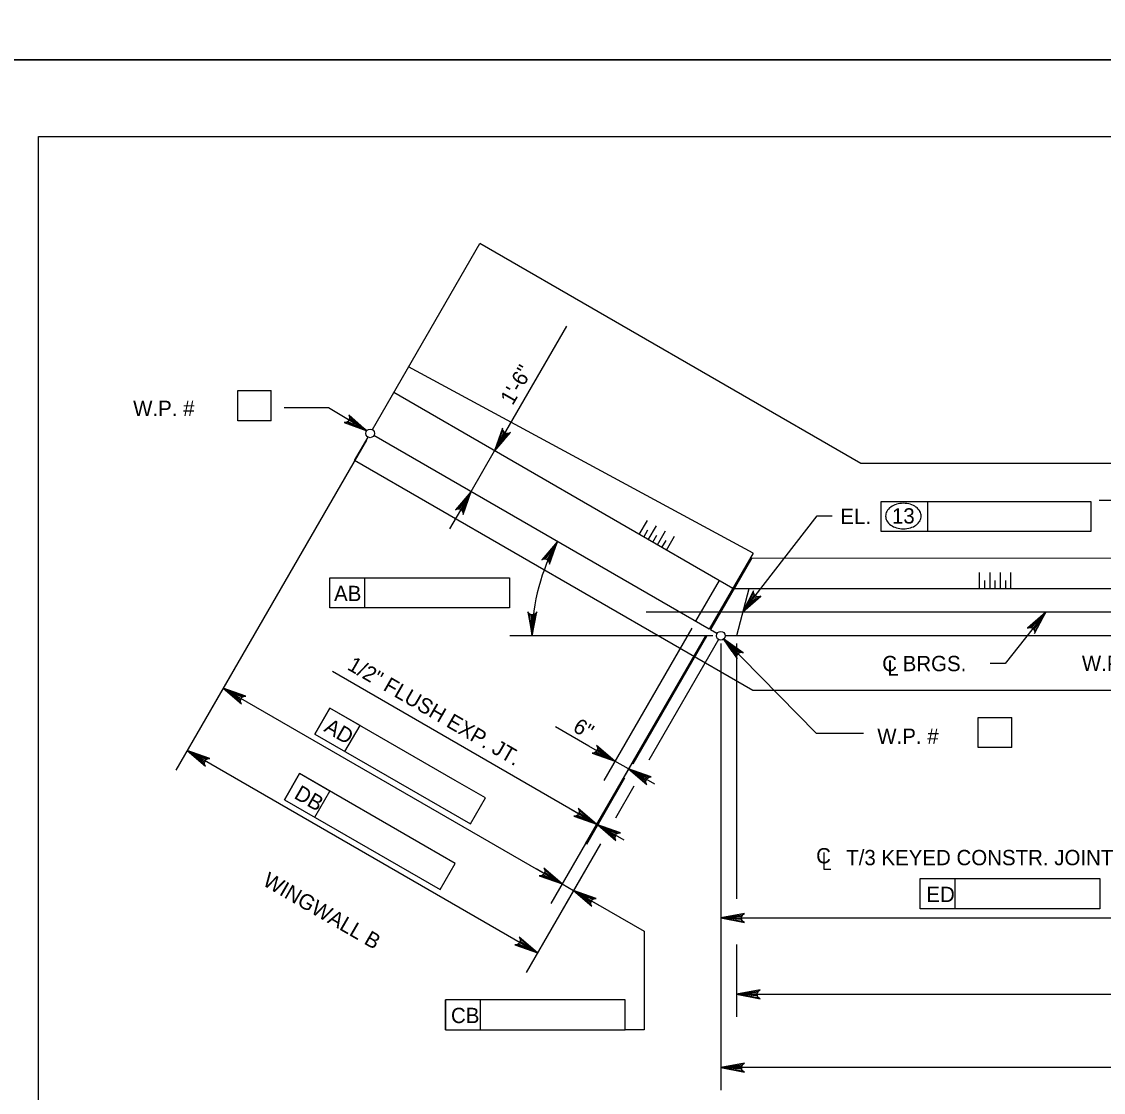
# Model space of a CAD drawing. Extents: x 638340 to 640242, y 295465 to 298435.
# Drawn here: x 638472.1 to 638684.2, y 297045 to 297255 of the extents above; entities that cross this region are included whole.
import ezdxf

# ---------------------------------------------------------------- set-up
doc = ezdxf.new("R2010")
doc.units = 0
for name, color, linetype in [('2', 7, 'Continuous'), ('Level 10', 7, 'Continuous'), ('Level 2', 7, 'Continuous'), ('Level 3', 7, 'Continuous'), ('PLT-BNDY', 7, 'Continuous')]:
    doc.layers.add(name, color=color, linetype=linetype)

msp = doc.modelspace()

# ---------------------------------------------------------------- linework, layer by layer
at = {"layer": '2'}
for p, q in [((638475.46, 296668.46), (638475.46, 297232.46)), ((638475.46, 297232.46), (639261.46, 297232.46))]:
    msp.add_line(p, q, dxfattribs=at)
at = {"layer": 'Level 10'}
for p, q in [((638540.91, 297174.98), (638561.98, 297211.46)), ((638636.67, 297168.34), (638561.98, 297211.46)), ((638615.56, 297150.77), (638548, 297187.26)), ((638611.56, 297143.84), (638545.09, 297182.22)), ((638537.42, 297168.92), (638540.06, 297173.51)), ((638606.95, 297135.87), (638541.22, 297173.82)), ((638615.53, 297123.83), (638537.42, 297168.92)), ((638810.57, 297168.34), (638636.67, 297168.34)), ((638615.56, 297150.77), (638606.95, 297135.87)), ((638615.29, 297149.79), (638607.17, 297135.74)), ((638615.29, 297149.79), (638831.04, 297149.87)), ((638608.9, 297145.38), (638604.29, 297137.4)), ((638834.55, 297143.78), (638611.82, 297143.78)), ((638614.73, 297143.78), (638612.27, 297134.57)), ((638859.26, 297139.18), (638594.57, 297139.18)), ((638608.46, 297135), (638607.17, 297135.74)), ((638724.77, 297134.57), (638610.05, 297134.57)), ((638834.78, 297123.83), (638615.53, 297123.83))]:
    msp.add_line(p, q, dxfattribs=at)
at = {"layer": 'Level 2'}
for p, q in [((638593.24, 297154.42), (638594.82, 297157.15)), ((638594.13, 297153.91), (638594.94, 297155.31)), ((638595.01, 297153.39), (638596.59, 297156.12)), ((638596.79, 297152.37), (638598.36, 297155.1)), ((638595.9, 297152.88), (638596.71, 297154.28)), ((638597.67, 297151.86), (638598.48, 297153.26)), ((638598.56, 297151.35), (638600.14, 297154.08)), ((638659.97, 297143.78), (638659.97, 297146.94)), ((638662.02, 297143.78), (638662.02, 297146.94)), ((638664.07, 297143.78), (638664.07, 297146.94)), ((638666.11, 297143.78), (638666.11, 297146.94)), ((638660.99, 297143.78), (638660.99, 297145.4)), ((638663.04, 297143.78), (638663.04, 297145.4)), ((638665.09, 297143.78), (638665.09, 297145.4))]:
    msp.add_line(p, q, dxfattribs=at)
at = {"layer": 'Level 3'}
for p, q in [((638566.36, 297173.34), (638579, 297195.26)), ((638514.52, 297182.61), (638521.09, 297182.61)), ((638514.52, 297176.72), (638514.52, 297182.61)), ((638521.09, 297176.72), (638521.09, 297182.61)), ((638532.29, 297179.25), (638523.6, 297179.25)), ((638539.8, 297174.75), (638532.29, 297179.25)), ((638521.09, 297176.72), (638514.52, 297176.72)), ((638539.72, 297172.91), (638509.43, 297120.44)), ((638560.28, 297162.81), (638564.88, 297170.79)), ((638558.81, 297160.26), (638556.05, 297155.49)), ((638640.66, 297160.86), (638649.82, 297160.86)), ((638640.66, 297154.97), (638640.66, 297160.86)), ((638649.82, 297154.97), (638649.82, 297160.86)), ((638649.82, 297160.86), (638681.79, 297160.86)), ((638681.79, 297160.86), (638681.79, 297154.97)), ((638717.98, 297161.05), (638683.42, 297161.05)), ((638613.5, 297139.18), (638628.15, 297158.08)), ((638628.15, 297158.08), (638631.09, 297158.08)), ((638681.79, 297154.97), (638640.66, 297154.97)), ((638532.58, 297145.93), (638539.42, 297145.93)), ((638532.58, 297140.03), (638532.58, 297145.93)), ((638539.42, 297140.03), (638539.42, 297145.93)), ((638539.42, 297145.93), (638567.82, 297145.93)), ((638567.82, 297145.93), (638567.82, 297140.03)), ((638567.82, 297140.03), (638532.58, 297140.03)), ((638672.95, 297139.18), (638665, 297129.12)), ((638603.53, 297136.07), (638586.26, 297106.16)), ((638607.66, 297134.57), (638567.84, 297134.57)), ((638606.19, 297134.54), (638575.89, 297082.07)), ((638606.19, 297134.54), (638582.65, 297093.77)), ((638606.19, 297134.54), (638588.91, 297104.62)), ((638606.41, 297134.41), (638591.95, 297109.36)), ((638608.77, 297133.84), (638595.12, 297110.19)), ((638609.76, 297133.94), (638627.94, 297115.44)), ((638609.2, 297133.04), (638609.2, 297074.8)), ((638612.27, 297133.04), (638612.27, 297082.99)), ((638513.99, 297128.34), (638502.38, 297108.23)), ((638584.86, 297097.6), (638533.06, 297127.52)), ((638665, 297129.12), (638662.05, 297129.12)), ((638511.64, 297124.27), (638578.1, 297085.9)), ((638532.56, 297120.39), (638529.61, 297115.29)), ((638529.62, 297115.29), (638532.56, 297120.39)), ((638557.16, 297106.19), (638532.56, 297120.39)), ((638538.48, 297116.97), (638532.56, 297120.39)), ((638535.53, 297111.87), (638538.48, 297116.97)), ((638659.7, 297118.51), (638666.28, 297118.51)), ((638659.7, 297112.62), (638659.7, 297118.51)), ((638666.28, 297112.62), (638666.28, 297118.51)), ((638529.61, 297115.29), (638560.13, 297097.67)), ((638583.36, 297112.93), (638576.83, 297116.7)), ((638627.94, 297115.44), (638637.17, 297115.44)), ((638588.46, 297109.98), (638583.36, 297112.93)), ((638666.28, 297112.62), (638659.7, 297112.62)), ((638573.3, 297072.39), (638504.59, 297112.06)), ((638591.12, 297108.45), (638588.47, 297109.99)), ((638591.13, 297108.45), (638596.23, 297105.5)), ((638523.68, 297102.42), (638526.63, 297107.53)), ((638526.63, 297107.53), (638523.69, 297102.42)), ((638551.23, 297093.33), (638526.63, 297107.53)), ((638532.55, 297104.11), (638526.63, 297107.53)), ((638563.07, 297102.77), (638557.16, 297106.19)), ((638590.36, 297106.61), (638582.87, 297093.64)), ((638529.6, 297099.01), (638532.55, 297104.11)), ((638592.15, 297105.04), (638588.55, 297098.81)), ((638523.69, 297102.42), (638554.2, 297084.81)), ((638560.13, 297097.67), (638563.07, 297102.77)), ((638582.31, 297099.07), (638579.75, 297100.55)), ((638585.08, 297097.47), (638584.86, 297097.6)), ((638585.08, 297097.47), (638590.19, 297094.52)), ((638585.63, 297093.75), (638578.14, 297080.77)), ((638609.2, 297094.09), (638609.2, 297045.45)), ((638557.14, 297089.91), (638551.23, 297093.33)), ((638629.42, 297092.09), (638629.42, 297088.78)), ((638554.2, 297084.81), (638557.14, 297089.91)), ((638582.7, 297088.67), (638571.09, 297068.56)), ((638575.55, 297087.37), (638573, 297088.84)), ((638629.42, 297088.78), (638630.81, 297088.78)), ((638578.1, 297085.9), (638580.35, 297084.6)), ((638648.32, 297086.94), (638655.15, 297086.94)), ((638648.32, 297081.05), (638648.32, 297086.94)), ((638655.15, 297081.05), (638655.15, 297086.94)), ((638655.15, 297086.94), (638683.56, 297086.94)), ((638683.56, 297086.94), (638683.56, 297081.05)), ((638580.35, 297084.6), (638594.19, 297076.61)), ((638582.9, 297083.13), (638585.45, 297081.66)), ((638683.56, 297081.05), (638648.32, 297081.05)), ((638609.2, 297079.23), (638717.64, 297079.23)), ((638594.19, 297076.61), (638594.19, 297057.3)), ((638612.27, 297074.02), (638612.27, 297059.84)), ((638612.27, 297064.26), (638828.92, 297064.26)), ((638555.25, 297063.19), (638555.25, 297057.3)), ((638583.65, 297063.19), (638555.25, 297063.19)), ((638562.08, 297063.19), (638555.25, 297063.19)), ((638555.25, 297057.3), (638555.25, 297063.19)), ((638562.08, 297057.3), (638562.08, 297063.19)), ((638590.49, 297063.19), (638583.65, 297063.19)), ((638590.49, 297057.3), (638590.49, 297063.19)), ((638555.25, 297057.3), (638590.49, 297057.3)), ((638594.19, 297057.3), (638590.49, 297057.3)), ((638837.02, 297049.88), (638609.2, 297049.88))]:
    msp.add_line(p, q, dxfattribs=at)
for points in [[(638539.8, 297174.75), (638536.26, 297177.89), (638536.44, 297177.49), (638536.44, 297177.13), (638536.33, 297176.83), (638536.12, 297176.59), (638535.8, 297176.42), (638535.37, 297176.39), (638539.8, 297174.75), (638535.8, 297176.42), (638536.12, 297176.59), (638539.8, 297174.75), (638536.33, 297176.83), (638536.44, 297177.13), (638539.8, 297174.75), (638536.44, 297177.49)], [(638564.88, 297170.79), (638567.96, 297174.38), (638567.57, 297174.2), (638567.21, 297174.19), (638566.91, 297174.3), (638566.67, 297174.5), (638566.49, 297174.82), (638566.45, 297175.25), (638564.88, 297170.79), (638566.49, 297174.82), (638566.67, 297174.5), (638564.88, 297170.79), (638566.91, 297174.3), (638567.21, 297174.19), (638564.88, 297170.79), (638567.57, 297174.2)], [(638560.28, 297162.81), (638557.2, 297159.22), (638557.59, 297159.41), (638557.96, 297159.41), (638558.25, 297159.3), (638558.5, 297159.1), (638558.67, 297158.78), (638558.71, 297158.35), (638560.28, 297162.81), (638558.67, 297158.78), (638558.5, 297159.1), (638560.28, 297162.81), (638558.25, 297159.3), (638557.96, 297159.41), (638560.28, 297162.81), (638557.59, 297159.41)], [(638577.21, 297153.04), (638574.13, 297149.45), (638574.52, 297149.63), (638574.88, 297149.64), (638575.18, 297149.53), (638575.42, 297149.33), (638575.6, 297149.01), (638575.64, 297148.58), (638577.21, 297153.04), (638575.6, 297149.01), (638575.42, 297149.33), (638577.21, 297153.04), (638575.18, 297149.53), (638574.88, 297149.64), (638577.21, 297153.04), (638574.52, 297149.63)], [(638613.5, 297139.18), (638617.04, 297142.32), (638616.62, 297142.19), (638616.26, 297142.23), (638615.98, 297142.38), (638615.77, 297142.61), (638615.63, 297142.95), (638615.66, 297143.39), (638613.5, 297139.18), (638615.63, 297142.95), (638615.77, 297142.61), (638613.5, 297139.18), (638615.98, 297142.38), (638616.26, 297142.23), (638613.5, 297139.18), (638616.62, 297142.19)], [(638572.26, 297134.57), (638573.13, 297139.22), (638572.88, 297138.87), (638572.57, 297138.68), (638572.26, 297138.63), (638571.95, 297138.68), (638571.63, 297138.87), (638571.39, 297139.22), (638572.26, 297134.57), (638571.63, 297138.87), (638571.95, 297138.68), (638572.26, 297134.57), (638572.26, 297138.63), (638572.57, 297138.68), (638572.26, 297134.57), (638572.88, 297138.87)], [(638672.95, 297139.18), (638669.38, 297136.07), (638669.8, 297136.19), (638670.16, 297136.15), (638670.43, 297135.99), (638670.65, 297135.76), (638670.78, 297135.42), (638670.75, 297134.99), (638672.95, 297139.18), (638670.78, 297135.42), (638670.65, 297135.76), (638672.95, 297139.18), (638670.43, 297135.99), (638670.16, 297136.15), (638672.95, 297139.18), (638669.8, 297136.19)], [(638609.76, 297133.94), (638612.4, 297130.01), (638612.32, 297130.44), (638612.42, 297130.79), (638612.6, 297131.05), (638612.86, 297131.22), (638613.21, 297131.31), (638613.64, 297131.23), (638609.76, 297133.94), (638613.21, 297131.31), (638612.86, 297131.22), (638609.76, 297133.94), (638612.6, 297131.05), (638612.42, 297130.79), (638609.76, 297133.94), (638612.32, 297130.44)], [(638511.64, 297124.27), (638515.23, 297121.19), (638515.04, 297121.59), (638515.04, 297121.95), (638515.15, 297122.25), (638515.35, 297122.49), (638515.67, 297122.67), (638516.1, 297122.7), (638511.64, 297124.27), (638515.67, 297122.67), (638515.35, 297122.49), (638511.64, 297124.27), (638515.15, 297122.25), (638515.04, 297121.95), (638511.64, 297124.27), (638515.04, 297121.59)], [(638588.46, 297109.98), (638584.87, 297113.07), (638585.06, 297112.67), (638585.06, 297112.31), (638584.95, 297112.01), (638584.75, 297111.77), (638584.43, 297111.59), (638584, 297111.56), (638588.46, 297109.98), (638584.43, 297111.59), (638584.75, 297111.77), (638588.46, 297109.98), (638584.95, 297112.01), (638585.06, 297112.31), (638588.46, 297109.98), (638585.06, 297112.67)], [(638504.59, 297112.06), (638508.18, 297108.98), (638507.99, 297109.37), (638507.99, 297109.73), (638508.1, 297110.03), (638508.3, 297110.27), (638508.62, 297110.45), (638509.05, 297110.49), (638504.59, 297112.06), (638508.62, 297110.45), (638508.3, 297110.27), (638504.59, 297112.06), (638508.1, 297110.03), (638507.99, 297109.73), (638504.59, 297112.06), (638507.99, 297109.37)], [(638591.13, 297108.45), (638594.72, 297105.37), (638594.53, 297105.76), (638594.53, 297106.13), (638594.64, 297106.42), (638594.84, 297106.66), (638595.16, 297106.84), (638595.59, 297106.88), (638591.13, 297108.45), (638595.16, 297106.84), (638594.84, 297106.66), (638591.13, 297108.45), (638594.64, 297106.42), (638594.53, 297106.13), (638591.13, 297108.45), (638594.53, 297105.76)], [(638584.86, 297097.6), (638581.27, 297100.68), (638581.45, 297100.29), (638581.46, 297099.92), (638581.35, 297099.63), (638581.14, 297099.38), (638580.83, 297099.2), (638580.39, 297099.17), (638584.86, 297097.6), (638580.83, 297099.2), (638581.14, 297099.38), (638584.86, 297097.6), (638581.35, 297099.63), (638581.46, 297099.92), (638584.86, 297097.6), (638581.45, 297100.29)], [(638585.08, 297097.47), (638588.67, 297094.39), (638588.49, 297094.78), (638588.48, 297095.15), (638588.59, 297095.44), (638588.79, 297095.69), (638589.11, 297095.86), (638589.54, 297095.9), (638585.08, 297097.47), (638589.11, 297095.86), (638588.79, 297095.69), (638585.08, 297097.47), (638588.59, 297095.44), (638588.48, 297095.15), (638585.08, 297097.47), (638588.49, 297094.78)], [(638578.1, 297085.9), (638574.51, 297088.98), (638574.7, 297088.58), (638574.7, 297088.22), (638574.59, 297087.93), (638574.39, 297087.68), (638574.07, 297087.5), (638573.64, 297087.47), (638578.1, 297085.9), (638574.07, 297087.5), (638574.39, 297087.68), (638578.1, 297085.9), (638574.59, 297087.93), (638574.7, 297088.22), (638578.1, 297085.9), (638574.7, 297088.58)], [(638580.35, 297084.6), (638583.94, 297081.52), (638583.75, 297081.92), (638583.75, 297082.28), (638583.86, 297082.58), (638584.06, 297082.82), (638584.38, 297083), (638584.81, 297083.03), (638580.35, 297084.6), (638584.38, 297083), (638584.06, 297082.82), (638580.35, 297084.6), (638583.86, 297082.58), (638583.75, 297082.28), (638580.35, 297084.6), (638583.75, 297081.92)], [(638609.2, 297079.23), (638613.85, 297078.35), (638613.49, 297078.6), (638613.31, 297078.91), (638613.25, 297079.23), (638613.31, 297079.54), (638613.49, 297079.85), (638613.85, 297080.1), (638609.2, 297079.23), (638613.49, 297079.85), (638613.31, 297079.54), (638609.2, 297079.23), (638613.25, 297079.23), (638613.31, 297078.91), (638609.2, 297079.23), (638613.49, 297078.6)], [(638573.3, 297072.39), (638569.7, 297075.47), (638569.89, 297075.08), (638569.89, 297074.71), (638569.78, 297074.42), (638569.58, 297074.17), (638569.27, 297073.99), (638568.83, 297073.96), (638573.3, 297072.39), (638569.27, 297073.99), (638569.58, 297074.17), (638573.3, 297072.39), (638569.78, 297074.42), (638569.89, 297074.71), (638573.3, 297072.39), (638569.89, 297075.08)], [(638612.27, 297064.26), (638616.92, 297063.39), (638616.56, 297063.64), (638616.38, 297063.95), (638616.32, 297064.26), (638616.38, 297064.57), (638616.56, 297064.89), (638616.92, 297065.13), (638612.27, 297064.26), (638616.56, 297064.89), (638616.38, 297064.57), (638612.27, 297064.26), (638616.32, 297064.26), (638616.38, 297063.95), (638612.27, 297064.26), (638616.56, 297063.64)], [(638609.2, 297049.88), (638613.85, 297049), (638613.49, 297049.25), (638613.31, 297049.56), (638613.25, 297049.88), (638613.31, 297050.19), (638613.49, 297050.5), (638613.85, 297050.75), (638609.2, 297049.88), (638613.49, 297050.5), (638613.31, 297050.19), (638609.2, 297049.88), (638613.25, 297049.88), (638613.31, 297049.56), (638609.2, 297049.88), (638613.49, 297049.25)]]:
    msp.add_lwpolyline(points, dxfattribs=at)
for points in [[(638537.02, 297175.84), (638537.53, 297176.68), (638539.8, 297174.75)], [(638565.93, 297173.59), (638566.78, 297173.1), (638564.88, 297170.79)], [(638558.38, 297160.51), (638559.23, 297160.02), (638560.28, 297162.81)], [(638615.69, 297141.21), (638614.92, 297141.81), (638613.5, 297139.18)], [(638670.73, 297137.17), (638671.51, 297136.56), (638672.95, 297139.18)], [(638612.17, 297132.18), (638611.47, 297131.49), (638609.76, 297133.94)], [(638514.44, 297123.22), (638513.94, 297122.37), (638511.64, 297124.27)], [(638507.38, 297111.01), (638506.89, 297110.16), (638504.59, 297112.06)], [(638586.16, 297111.88), (638585.67, 297111.03), (638588.47, 297109.99)], [(638593.92, 297107.4), (638593.43, 297106.55), (638591.12, 297108.45)], [(638582.55, 297099.5), (638582.06, 297098.65), (638584.86, 297097.6)], [(638587.88, 297096.42), (638587.39, 297095.57), (638585.08, 297097.47)], [(638575.8, 297087.8), (638575.31, 297086.95), (638578.1, 297085.9)], [(638583.14, 297083.55), (638582.65, 297082.7), (638580.35, 297084.6)], [(638612.14, 297079.72), (638612.14, 297078.73), (638609.2, 297079.23)], [(638570.99, 297074.29), (638570.5, 297073.44), (638573.3, 297072.39)], [(638615.21, 297064.75), (638615.21, 297063.77), (638612.27, 297064.26)], [(638612.14, 297050.37), (638612.14, 297049.38), (638609.2, 297049.88)]]:
    msp.add_lwpolyline(points, close=True, dxfattribs=at)
for centre in [(638540.49, 297174.24), (638609.2, 297134.57)]:
    msp.add_circle(centre, 0.849, dxfattribs=at)
for centre, radius, start, end in [((638644.16, 297157.56), 2.75, 125.6316, 149.9767), ((638644.69, 297156.82), 3.65, 106.5358, 125.6316), ((638645.03, 297155.67), 4.86, 90, 106.5358), ((638645.03, 297155.67), 4.86, 73.4642, 90), ((638645.37, 297156.82), 3.65, 54.3684, 73.4642), ((638645.9, 297157.56), 2.75, 30.0233, 54.3684), ((638643.36, 297158.02), 1.82, 149.9767, 180), ((638643.36, 297158.02), 1.82, 180, 210.0233), ((638644.16, 297158.49), 2.75, 210.0233, 234.3684), ((638645.9, 297158.49), 2.75, 305.6316, 329.9767), ((638646.7, 297158.02), 1.82, 0, 30.0233), ((638646.7, 297158.02), 1.82, 329.9767, 0), ((638644.69, 297159.22), 3.65, 234.3684, 253.4642), ((638645.03, 297160.38), 4.86, 253.4642, 270), ((638645.03, 297160.38), 4.86, 270, 286.5358), ((638645.37, 297159.22), 3.65, 286.5358, 305.6316), ((638609.2, 297134.57), 36.94, 149.9994, 179.9989)]:
    msp.add_arc(centre, radius, start, end, dxfattribs=at)
at = {"layer": 'PLT-BNDY'}
for points in [[(638435.46, 297841.46), (639276.46, 297841.46), (639276.46, 297247.46), (638435.46, 297247.46)], [(638435.46, 297247.46), (639276.46, 297247.46), (639276.46, 296653.46), (638435.46, 296653.46)]]:
    msp.add_lwpolyline(points, close=True, dxfattribs=at)

# ---------------------------------------------------------------- texts
at = {"layer": 'Level 3'}
for s, height, rotation, p in [('1\'-6"', 3, 60, (638568.41, 297179.58)), ('1/2" FLUSH EXP. JT.', 3.0001, 330, (638535.8, 297128.05)), ('AD', 3, 330, (638531.22, 297115.92)), ('6"', 3, 330, (638580.01, 297115.95)), ('DB', 3, 330, (638525.35, 297102.81)), ('WINGWALL B', 3, 330, (638519.18, 297085.76))]:
    msp.add_text(s, height=height, rotation=rotation, dxfattribs=at).set_placement(p)
for s, height, p in [('W.P. #', 3, (638493.99, 297177.64)), ('EL.', 3, (638632.66, 297156.45)), ('13', 3, (638642.78, 297156.56)), ('AB', 3, (638533.39, 297141.35)), ('C BRGS.', 3, (638640.87, 297127.61)), ('L', 3, (638641.89, 297126.73)), ('W.P.#', 3, (638680.02, 297127.67)), ('W.P. #', 3, (638639.9, 297113.36)), ('C', 3, (638627.92, 297089.93)), ('T/3 KEYED CONSTR. JOINT', 3.0001, (638633.81, 297089.57)), ('ED', 3, (638649.53, 297082.35)), ('CB', 3, (638556.32, 297058.62))]:
    msp.add_text(s, height=height, dxfattribs=at).set_placement(p)

doc.saveas('drawing.dxf')
